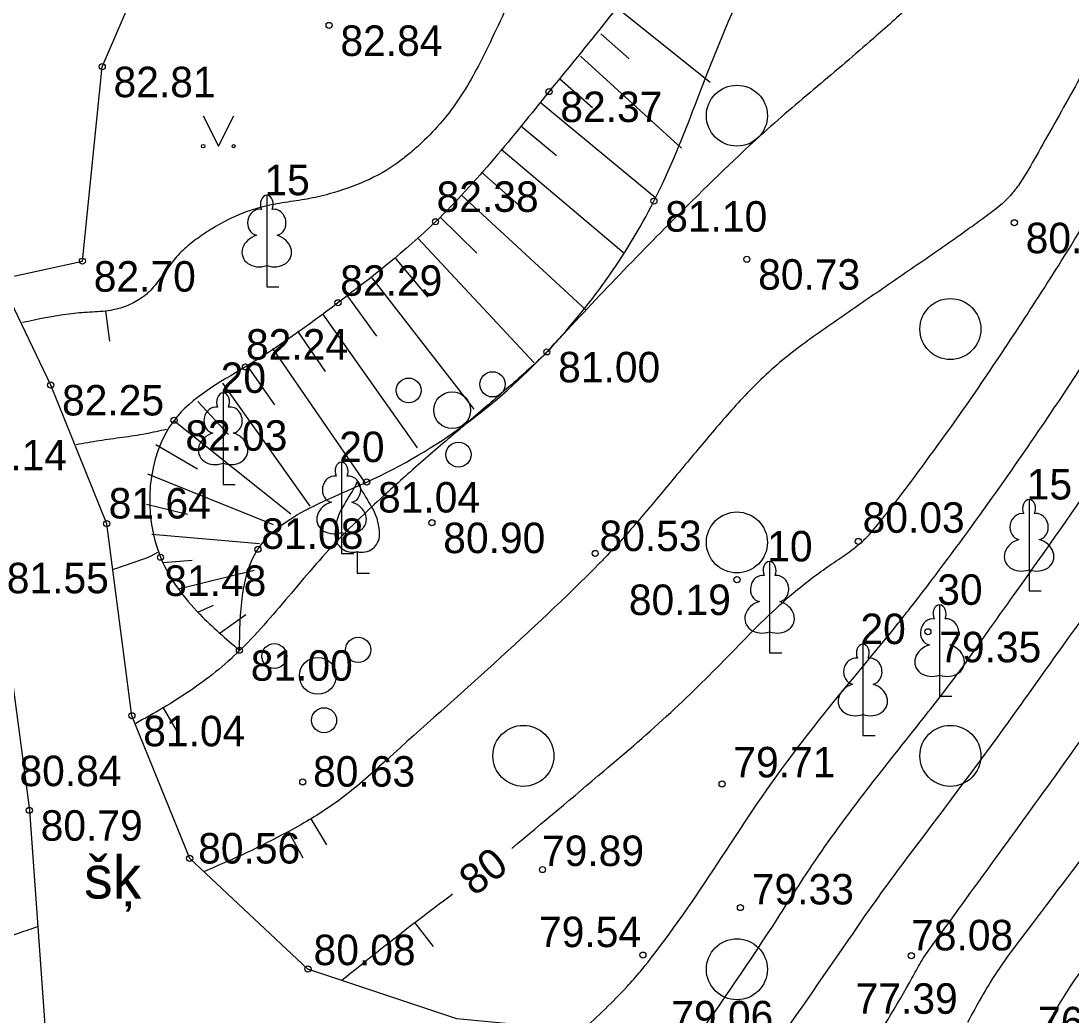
# Model space of a CAD drawing. Extents: x 576692 to 577659, y 273254 to 273799.
# Drawn here: x 577229.26 to 577246.48, y 273433.25 to 273449.55 of the extents above; entities that cross this region are included whole.
import ezdxf

# ---------------------------------------------------------------- set-up
doc = ezdxf.new("R2010")
doc.units = 0
for name, color, linetype in [('APGR_SARK_####_####_#', 7, 'Continuous'), ('CELI_CAPM_####_####_#', 7, 'Continuous'), ('CELI_CMAL_####_####_#', 7, 'Continuous'), ('DREN_VADP_####_####_#', 7, 'Continuous'), ('GAZE_ELEM_####_####_#', 7, 'Continuous'), ('GEOD_ELEM_####_TKST_#', 7, 'Continuous'), ('GEOD_SITP_####_TKST_#', 7, 'Continuous'), ('HIDT_REZV_####_TKST_#', 7, 'Continuous'), ('LKAN_ELEM_PAST_TKST_#', 7, 'Continuous'), ('RELJ_ELEM_####_####_#', 7, 'Continuous'), ('RELJ_HORZ_PAMT_####_#', 7, 'Continuous'), ('SAKT_ELEM_####_####_#', 7, 'Continuous')]:
    doc.layers.add(name, color=color, linetype=linetype)

msp = doc.modelspace()

# ---------------------------------------------------------------- linework, layer by layer
at = {"layer": 'CELI_CAPM_####_####_#'}
for points in [[(577228.923, 273445.318), (577230.27, 273445.614), (577230.595, 273448.803), (577231.355, 273450.566), (577234.085, 273452.032), (577237.485, 273453.435)], [(577239.967, 273432.847), (577236.409, 273433.185), (577233.967, 273434.004), (577232.029, 273435.819), (577231.081, 273438.157), (577230.668, 273441.308), (577229.75, 273443.582), (577228.923, 273445.318)], [(577226.894, 273444.872), (577228.158, 273442.682), (577228.94, 273440.111), (577229.4, 273436.607), (577229.647, 273433.16), (577229.46, 273430.823), (577228.732, 273429.286), (577226.937, 273426.456), (577227.852, 273423.261), (577230.447, 273423.509), (577231.567, 273426.352), (577233.509, 273429.564), (577235.536, 273430.991), (577239.635, 273431.907)]]:
    msp.add_lwpolyline(points, dxfattribs=at)
at = {"layer": 'DREN_VADP_####_####_#'}
msp.add_spline([(577252.982, 273414.853), (577251.974, 273414.319), (577251.296, 273413.895), (577249.566, 273411.91), (577248.903, 273411.509), (577248.444, 273411.498), (577247.696, 273411.504), (577246.444, 273411.535), (577244.846, 273411.363), (577244.022, 273411.247), (577241.708, 273410.879), (577240.339, 273410.502), (577239, 273410.046), (577237.665, 273409.574), (577236.308, 273409.148), (577232.395, 273408.229), (577230.233, 273408.289), (577228.16, 273408.614), (577226.772, 273408.795), (577225.035, 273408.894), (577216.714, 273409.044), (577215.802, 273409.128), (577214.183, 273409.253), (577210.948, 273409.331), (577207.808, 273409.112), (577206.24, 273408.92), (577204.358, 273408.692), (577200.757, 273408.499), (577197.064, 273408.225), (577195.293, 273408.274), (577193.884, 273408.307), (577192.404, 273408.351), (577191.034, 273408.298), (577188.672, 273408.17), (577187.769, 273408), (577187.12, 273407.732), (577186.576, 273407.527), (577186.03, 273407.46), (577185.261, 273408.176), (577184.947, 273408.486), (577184.626, 273408.818), (577184.295, 273409.183), (577183.826, 273409.606), (577182.671, 273410.193), (577181.38, 273410.806), (577180.079, 273411.403), (577178.701, 273412.153), (577176.151, 273413.713), (577175.37, 273414.363), (577174.894, 273414.947), (577174.466, 273415.545), (577174.114, 273416.004), (577171.235, 273418.393), (577170.422, 273418.755), (577169.358, 273419.229), (577168.284, 273419.699), (577167.376, 273420.223), (577166.523, 273421.019), (577166.325, 273421.442), (577166.264, 273421.836), (577166.208, 273422.249), (577166.113, 273422.474), (577165.735, 273422.577), (577165.493, 273422.415), (577164.833, 273422.237), (577164.536, 273422.311), (577162.044, 273423.335), (577157.906, 273424.803), (577155.548, 273425.078), (577154.221, 273424.995), (577152.73, 273424.792), (577149.601, 273423.667), (577149.132, 273423.331), (577148.389, 273422.813), (577147.644, 273422.309), (577147.083, 273422.041), (577145.741, 273421.593), (577144.586, 273421.422), (577143.433, 273421.242), (577142.637, 273421.093), (577137.334, 273418.585), (577135.002, 273417.571), (577133.759, 273417.478), (577132.689, 273417.77), (577131.611, 273418.15), (577130.554, 273418.322), (577129.877, 273418.108), (577129.214, 273417.682), (577128.473, 273417.311), (577127.7, 273417.376), (577125.9, 273418.627), (577123.805, 273421.904), (577122.752, 273424.503), (577122.635, 273425.088), (577122.595, 273425.692), (577122.541, 273426.294), (577122.379, 273426.874), (577120.633, 273429.122), (577118.876, 273430.502), (577117.365, 273431.308), (577114.934, 273432.161), (577112.354, 273432.529), (577111.381, 273432.669), (577110.378, 273432.861), (577108.182, 273433.552), (577106.895, 273434.234)], degree=3, dxfattribs=at)
at = {"layer": 'GAZE_ELEM_####_####_#'}
for p, q in [((577239.093, 273449.726), (577240.562, 273448.548)), ((577238.769, 273449.345), (577239.233, 273448.93)), ((577238.434, 273448.974), (577240.092, 273447.466)), ((577238.099, 273448.602), (577238.634, 273448.134)), ((577237.777, 273448.22), (577239.671, 273446.65)), ((577237.458, 273447.835), (577238.045, 273447.347)), ((577237.137, 273447.452), (577239.147, 273445.749)), ((577236.812, 273447.072), (577237.424, 273446.534)), ((577236.478, 273446.7), (577238.523, 273444.817)), ((577236.135, 273446.336), (577236.736, 273445.746)), ((577235.777, 273445.987), (577237.677, 273443.946)), ((577235.402, 273445.656), (577235.934, 273445.022)), ((577235.013, 273445.342), (577236.686, 273443.184)), ((577234.614, 273445.041), (577235.094, 273444.386)), ((577234.207, 273444.751), (577235.76, 273442.55)), ((577233.796, 273444.466), (577234.252, 273443.802)), ((577233.384, 273444.183), (577234.904, 273441.972)), ((577232.972, 273443.899), (577233.42, 273443.257)), ((577232.564, 273443.61), (577234, 273441.597)), ((577232.161, 273443.314), (577232.664, 273442.773)), ((577231.771, 273443.002), (577233.686, 273441.47)), ((577231.473, 273442.605), (577232.155, 273442.206)), ((577231.336, 273442.126), (577233.396, 273441.293)), ((577231.32, 273441.627), (577231.991, 273441.465)), ((577231.406, 273441.135), (577233.172, 273440.983)), ((577231.593, 273440.673), (577232.071, 273440.707)), ((577231.844, 273440.241), (577233.084, 273440.545)), ((577232.161, 273439.855), (577232.421, 273439.972)), ((577232.53, 273439.518), (577232.951, 273439.819))]:
    msp.add_line(p, q, dxfattribs=at)
msp.add_spline([(577242.91, 273457.86), (577239.725, 273450.721), (577237.921, 273448.394), (577236.059, 273446.259), (577234.46, 273444.93), (577232.943, 273443.878), (577231.772, 273443.003), (577231.55, 273440.757), (577232.196, 273439.822), (577232.844, 273439.231)], degree=3, dxfattribs=at)
at = {"layer": 'GEOD_ELEM_####_TKST_#'}
msp.add_line((577236.025, 273434.372), (577235.721, 273434.769), dxfattribs=at)
for points in [[(577237.31, 273435.982), (577238.817, 273437.25), (577239.916, 273438.213), (577240.915, 273439.193), (577241.896, 273440.146), (577242.448, 273440.573), (577242.738, 273440.771), (577243.018, 273440.982), (577243.168, 273441.126), (577243.387, 273441.392), (577243.6, 273441.662), (577244.014, 273442.212), (577244.813, 273443.324), (577245.577, 273444.46), (577246.317, 273445.612), (577247.158, 273447.012), (577248.372, 273449.267), (577248.708, 273449.952)], [(577242.989, 273432.39), (577243.833, 273433.786), (577243.979, 273434.05), (577244.056, 273434.183), (577244.109, 273434.259), (577246.227, 273437.18), (577247.574, 273439.066), (577249.555, 273441.831), (577250.237, 273442.898), (577251.648, 273445.512)], [(577230.168, 273442.608), (577230.547, 273442.673), (577230.928, 273442.727), (577231.308, 273442.787), (577231.648, 273442.858)], [(577234.53, 273433.826), (577235.659, 273434.721), (577236.34, 273435.236)], [(577255.711, 273434.536), (577255.546, 273434.378), (577255.423, 273434.179), (577255.334, 273433.957), (577255.275, 273433.726), (577255.251, 273433.553), (577255.249, 273433.38), (577255.278, 273433.047), (577255.332, 273432.714), (577255.384, 273432.382), (577255.406, 273432.049), (577255.393, 273431.875), (577255.352, 273431.705), (577255.285, 273431.538), (577255.194, 273431.373), (577255.069, 273431.225), (577254.994, 273431.168), (577254.909, 273431.122), (577254.731, 273431.075), (577254.543, 273431.072), (577254.355, 273431.07), (577254.18, 273431.022), (577253.884, 273430.789), (577253.746, 273430.581), (577253.635, 273430.359), (577253.523, 273430.14), (577253.38, 273429.943), (577253.105, 273429.645), (577252.819, 273429.36), (577252.519, 273429.095), (577252.199, 273428.852), (577251.899, 273428.646), (577251.649, 273428.477), (577250.896, 273427.978), (577250.396, 273427.641), (577250.148, 273427.47), (577249.902, 273427.295), (577249.672, 273427.116), (577249.45, 273426.925), (577249.232, 273426.73), (577249.01, 273426.54), (577248.703, 273426.289), (577248.214, 273425.925), (577245.673, 273423.793), (577245.544, 273423.668), (577245.335, 273423.423), (577245.132, 273423.166)]]:
    msp.add_spline(points, degree=3, dxfattribs=at)
at = {"layer": 'GEOD_SITP_####_TKST_#'}
for p, q in [((577230.717, 273444.3), (577230.656, 273444.796)), ((577231.85, 273437.857), (577231.598, 273438.289)), ((577234.275, 273436.038), (577234.021, 273436.468)), ((577233.887, 273435.82), (577233.649, 273436.26))]:
    msp.add_line(p, q, dxfattribs=at)
for points in [[(577248.408, 273456.577), (577248.253, 273456.237), (577247.855, 273455.516), (577247.448, 273454.733), (577247.054, 273453.943), (577246.659, 273453.152), (577246.247, 273452.369), (577245.6, 273451.5), (577245.025, 273450.923), (577244.44, 273450.36), (577243.845, 273449.809), (577243.24, 273449.268), (577242.777, 273448.869), (577242.311, 273448.475), (577241.846, 273448.079), (577241.389, 273447.674), (577240.023, 273446.358), (577237.898, 273444.133), (577237.886, 273444.12), (577237.867, 273444.101), (577237.22, 273443.515), (577236.558, 273442.945), (577235.895, 273442.377), (577235.243, 273441.796), (577234.519, 273441.099), (577234.099, 273440.643), (577233.697, 273440.171), (577233.293, 273439.701), (577232.869, 273439.249), (577232.846, 273439.227), (577232.842, 273439.223), (577232.036, 273438.569), (577231.595, 273438.287), (577231.144, 273438.032)], [(577242.058, 273455.968), (577241.903, 273455.789), (577241.747, 273455.608), (577241.462, 273455.227), (577239.94, 273452.789), (577239.849, 273452.645), (577239.724, 273452.516), (577239.43, 273452.321), (577239.106, 273452.169), (577238.786, 273452.01), (577238.505, 273451.795), (577238.355, 273451.63), (577238.212, 273451.462), (577237.948, 273451.113), (577237.713, 273450.748), (577237.506, 273450.365), (577236.99, 273449.277), (577236.728, 273448.754), (577236.487, 273448.341), (577236.206, 273447.956), (577235.88, 273447.602), (577235.699, 273447.436), (577235.507, 273447.279), (577234.975, 273446.955), (577234.402, 273446.741), (577234.046, 273446.65), (577233.683, 273446.59), (577233.322, 273446.526), (577232.968, 273446.426), (577232.461, 273446.186), (577232.224, 273446.034), (577231.997, 273445.863), (577231.791, 273445.66), (577231.616, 273445.425), (577231.438, 273445.193), (577231.338, 273445.087), (577231.281, 273445.041), (577231.219, 273444.998), (577230.985, 273444.876), (577230.735, 273444.807), (577230.563, 273444.787), (577230.391, 273444.776), (577230.219, 273444.765), (577230.048, 273444.747), (577229.288, 273444.605)], [(577249.575, 273455.482), (577249.485, 273455.222), (577249.43, 273455.059), (577249.335, 273454.759), (577249.245, 273454.458), (577249.156, 273454.156), (577249.061, 273453.856), (577248.645, 273452.759), (577248.411, 273452.221), (577248.17, 273451.684), (577247.645, 273450.575), (577247.089, 273449.485), (577246.507, 273448.407), (577245.905, 273447.334), (577245.65, 273446.907), (577245.501, 273446.71), (577245.326, 273446.536), (577245.066, 273446.334), (577244.799, 273446.142), (577244.049, 273445.616), (577243.294, 273445.097), (577242.541, 273444.574), (577241.8, 273444.033), (577241.093, 273443.367), (577240.53, 273442.726), (577239.984, 273442.072), (577239.437, 273441.419), (577238.871, 273440.784), (577238.748, 273440.658), (577235.26, 273437.435), (577234.551, 273436.828), (577233.901, 273436.399), (577233.501, 273436.181), (577233.097, 273435.975), (577232.27, 273435.604)], [(577238.465, 273432.992), (577239.2, 273433.717), (577239.418, 273433.965), (577239.734, 273434.366), (577240.902, 273436.063), (577241.25, 273436.591), (577242.601, 273438.403), (577243.641, 273439.669), (577243.837, 273439.918), (577245.953, 273442.834), (577247.249, 273444.846), (577248.916, 273447.851), (577250.42, 273450.936), (577250.943, 273452.34), (577251.155, 273452.959), (577251.484, 273453.704)], [(577240.276, 273432.78), (577241.672, 273434.839), (577242.23, 273435.702), (577244.06, 273438.12), (577244.676, 273438.923), (577245.026, 273439.413), (577245.536, 273440.129), (577246.905, 273442.085), (577247.577, 273443.071), (577248.242, 273444.064), (577248.782, 273444.993), (577250.646, 273448.677), (577251.416, 273450.272), (577251.693, 273450.991), (577251.991, 273451.827), (577252.437, 273452.815)], [(577241.457, 273432.508), (577242.849, 273434.507), (577243.117, 273434.896), (577243.954, 273436.038), (577245.451, 273438.052), (577246.3, 273439.24), (577247.541, 273440.978), (577249.165, 273443.524), (577252.22, 273449.224), (577252.357, 273449.493), (577252.413, 273449.609), (577252.434, 273449.66), (577252.826, 273450.695), (577253.389, 273451.89)], [(577255.267, 273450.117), (577254.891, 273449.377), (577254.49, 273448.441), (577254.279, 273447.983), (577251.699, 273443.039), (577251.314, 273442.346), (577251.137, 273442.074), (577249.369, 273439.639), (577248.836, 273438.894), (577247.007, 273436.303), (577245.652, 273434.495), (577245.256, 273433.946), (577244.78, 273433.126)], [(577256.236, 273449.251), (577255.786, 273448.386), (577255.32, 273447.317), (577255.237, 273447.14), (577254.2, 273445.187), (577252.393, 273441.99), (577251.595, 273440.737), (577249.946, 273438.448), (577249.632, 273438.021), (577248.523, 273436.46), (577247.792, 273435.421), (577247.248, 273434.738), (577246.457, 273433.709), (577246.042, 273433.007)], [(577230.767, 273440.557), (577230.795, 273440.566), (577230.833, 273440.58), (577231.459, 273440.814), (577231.509, 273440.842)], [(577229.528, 273434.696), (577228.811, 273434.44), (577228.093, 273434.163), (577227.077, 273433.74), (577226.625, 273433.614), (577225.865, 273433.58), (577224.619, 273433.686), (577222.91, 273433.78), (577222.886, 273433.785), (577222.863, 273433.793), (577222.831, 273433.805), (577218.391, 273435.021), (577215.702, 273435.502), (577212.683, 273435.835), (577211.95, 273435.848), (577210.689, 273435.795), (577208.153, 273435.708), (577204.598, 273435.61), (577203.143, 273435.592), (577196.078, 273435.666), (577195.486, 273435.681), (577195.463, 273435.683), (577195.34, 273435.701), (577194.109, 273435.908), (577192.883, 273436.138), (577191.66, 273436.393), (577190.441, 273436.675), (577188.159, 273437.582), (577187.574, 273437.944), (577187.005, 273438.321), (577186.056, 273439.02)]]:
    msp.add_spline(points, degree=3, dxfattribs=at)
at = {"layer": 'LKAN_ELEM_PAST_TKST_#'}
for p, q in [((577232.25, 273448), (577232.5, 273447.5)), ((577232.5, 273447.5), (577232.75, 273448)), ((577233.293, 273445.542), (577233.293, 273445.195)), ((577233.293, 273445.195), (577233.493, 273445.195)), ((577232.576, 273442.299), (577232.576, 273441.952)), ((577232.576, 273441.952), (577232.776, 273441.952)), ((577234.519, 273441.165), (577234.519, 273440.818)), ((577234.519, 273440.818), (577234.719, 273440.818)), ((577234.776, 273440.85), (577234.776, 273440.498)), ((577245.791, 273440.552), (577245.791, 273440.205)), ((577234.776, 273440.498), (577234.976, 273440.498)), ((577245.791, 273440.205), (577245.991, 273440.205)), ((577241.537, 273439.536), (577241.537, 273439.189)), ((577241.537, 273439.189), (577241.737, 273439.189)), ((577244.324, 273438.824), (577244.324, 273438.477)), ((577244.324, 273438.477), (577244.524, 273438.477)), ((577243.065, 273438.18), (577243.065, 273437.833)), ((577243.065, 273437.833), (577243.265, 273437.833))]:
    msp.add_line(p, q, dxfattribs=at)
for points in [[(577233.293, 273446.695), (577233.293, 273445.542)], [(577233.383, 273446.463), (577233.382, 273446.464)], [(577232.576, 273443.452), (577232.576, 273442.299)], [(577232.666, 273443.22), (577232.665, 273443.221)], [(577234.519, 273442.318), (577234.519, 273441.165)], [(577234.609, 273442.086), (577234.608, 273442.087)], [(577245.791, 273441.705), (577245.791, 273440.552)], [(577245.881, 273441.473), (577245.88, 273441.474)], [(577241.537, 273440.689), (577241.537, 273439.536)], [(577241.627, 273440.457), (577241.626, 273440.458)], [(577244.324, 273439.977), (577244.324, 273438.824)], [(577244.414, 273439.745), (577244.413, 273439.746)], [(577243.065, 273439.333), (577243.065, 273438.18)], [(577243.155, 273439.101), (577243.154, 273439.102)]]:
    msp.add_lwpolyline(points, dxfattribs=at)
for centre, radius in [((577241, 273448), 0.5), ((577232.25, 273447.5), 0.028), ((577232.75, 273447.5), 0.0263), ((577244.5, 273444.5), 0.5), ((577236.994, 273443.594), 0.207), ((577235.619, 273443.493), 0.204), ((577236.333, 273443.169), 0.301), ((577236.436, 273442.441), 0.205), ((577241, 273441), 0.5), ((577233.416, 273439.137), 0.204), ((577234.791, 273439.238), 0.207), ((577234.13, 273438.813), 0.301), ((577234.233, 273438.085), 0.205), ((577237.5, 273437.5), 0.5), ((577244.5, 273437.5), 0.5), ((577241, 273434), 0.5)]:
    msp.add_circle(centre, radius, dxfattribs=at)
for centre, radius, start, end in [((577234.359, 273442.136), 0.439, 324.3837, 341.712), ((577235.193, 273442.136), 0.439, 198.288, 215.6163), ((577247.401, 273434.102), 14.88, 148.4844, 149.9901), ((577222.151, 273434.102), 14.88, 30.0099, 31.5156), ((577235.3, 273441.123), 0.89, 151.757, 179.9138), ((577234.252, 273441.123), 0.89, 0.0862, 28.243), ((577234.7, 273441.129), 0.29, 181.0782, 285.2823), ((577234.852, 273441.129), 0.29, 254.7177, 358.9218)]:
    msp.add_arc(centre, radius, start, end, dxfattribs=at)
for centre, major_axis, ratio, start_param, end_param in [((577233.293, 273446.545), (0, -0.15), 0.707107, 3.14537, 5.287485), ((577233.293, 273446.545), (0, -0.15), 0.707107, 0.995701, 3.137816), ((577233.165, 273446.25), (-0.039, -0.212), 0.861323, 3.141593, 6.283185), ((577233.421, 273446.25), (0.039, -0.212), 0.861323, 0, 3.141593), ((577233.203, 273445.788), (0.307, 0.095), 0.814445, 1.570796, 4.752015), ((577233.383, 273445.788), (-0.307, 0.095), 0.814445, 1.531171, 4.712389), ((577232.576, 273443.302), (0, -0.15), 0.707107, 3.14537, 5.287485), ((577232.576, 273443.302), (0, -0.15), 0.707107, 0.995701, 3.137816), ((577232.448, 273443.007), (-0.039, -0.212), 0.861323, 3.141593, 6.283185), ((577232.704, 273443.007), (0.039, -0.212), 0.861323, 0, 3.141593), ((577232.486, 273442.545), (0.307, 0.095), 0.814445, 1.570796, 4.752015), ((577232.666, 273442.545), (-0.307, 0.095), 0.814445, 1.531171, 4.712389), ((577234.519, 273442.168), (0, -0.15), 0.707107, 3.14537, 5.287485), ((577234.519, 273442.168), (0, -0.15), 0.707107, 0.995701, 3.137816), ((577234.391, 273441.873), (-0.039, -0.212), 0.861323, 3.141593, 6.283185), ((577234.647, 273441.873), (0.039, -0.212), 0.861323, 0, 3.141593), ((577234.429, 273441.411), (0.307, 0.095), 0.814445, 1.570796, 4.752015), ((577234.609, 273441.411), (-0.307, 0.095), 0.814445, 1.531171, 4.712389), ((577245.791, 273441.555), (0, -0.15), 0.707107, 3.14537, 5.287485), ((577245.791, 273441.555), (0, -0.15), 0.707107, 0.995701, 3.137816), ((577245.663, 273441.26), (-0.039, -0.212), 0.861323, 3.141593, 6.283185), ((577245.919, 273441.26), (0.039, -0.212), 0.861323, 0, 3.141593), ((577245.701, 273440.798), (0.307, 0.095), 0.814445, 1.570796, 4.752015), ((577245.881, 273440.798), (-0.307, 0.095), 0.814445, 1.531171, 4.712389), ((577241.537, 273440.539), (0, -0.15), 0.707107, 3.14537, 5.287485), ((577241.537, 273440.539), (0, -0.15), 0.707107, 0.995701, 3.137816), ((577241.409, 273440.244), (-0.039, -0.212), 0.861323, 3.141593, 6.283185), ((577241.665, 273440.244), (0.039, -0.212), 0.861323, 0, 3.141593), ((577241.447, 273439.782), (0.307, 0.095), 0.814445, 1.570796, 4.752015), ((577241.627, 273439.782), (-0.307, 0.095), 0.814445, 1.531171, 4.712389), ((577244.324, 273439.827), (0, -0.15), 0.707107, 3.14537, 5.287485), ((577244.324, 273439.827), (0, -0.15), 0.707107, 0.995701, 3.137816), ((577244.196, 273439.532), (-0.039, -0.212), 0.861323, 3.141593, 6.283185), ((577244.452, 273439.532), (0.039, -0.212), 0.861323, 0, 3.141593), ((577243.065, 273439.183), (0, -0.15), 0.707107, 3.14537, 5.287485), ((577243.065, 273439.183), (0, -0.15), 0.707107, 0.995701, 3.137816), ((577244.234, 273439.07), (0.307, 0.095), 0.814445, 1.570796, 4.752015), ((577244.414, 273439.07), (-0.307, 0.095), 0.814445, 1.531171, 4.712389), ((577242.937, 273438.888), (-0.039, -0.212), 0.861323, 3.141593, 6.283185), ((577243.193, 273438.888), (0.039, -0.212), 0.861323, 0, 3.141593), ((577242.975, 273438.426), (0.307, 0.095), 0.814445, 1.570796, 4.752015), ((577243.155, 273438.426), (-0.307, 0.095), 0.814445, 1.531171, 4.712389)]:
    msp.add_ellipse(centre, major_axis=major_axis, ratio=ratio, start_param=start_param, end_param=end_param, dxfattribs=at)
at = {"layer": 'RELJ_ELEM_####_####_#'}
for centre in [(577234.314, 273449.48), (577230.595, 273448.803), (577237.92, 273448.395), (577239.639, 273446.598), (577236.059, 273446.26), (577245.549, 273446.244), (577241.163, 273445.646), (577230.27, 273445.614), (577234.46, 273444.931), (577237.884, 273444.126), (577232.943, 273443.879), (577229.75, 273443.583), (577231.772, 273443.004), (577234.931, 273441.991), (577230.668, 273441.309), (577236, 273441.325), (577242.991, 273441.017), (577233.147, 273440.889), (577238.677, 273440.82), (577231.55, 273440.757), (577241.002, 273440.39), (577244.132, 273439.535), (577232.844, 273439.232), (577231.081, 273438.157), (577233.882, 273437.073), (577240.757, 273437.039), (577229.4, 273436.608), (577232.029, 273435.82), (577237.813, 273435.635), (577241.059, 273435.012), (577239.46, 273434.232), (577243.861, 273434.221), (577233.968, 273434.004)]:
    msp.add_circle(centre, 0.05, dxfattribs=at)
at = {"layer": 'SAKT_ELEM_####_####_#'}
msp.add_spline([(577232.844, 273439.231), (577233.147, 273440.888), (577234.931, 273441.99), (577237.884, 273444.125), (577239.64, 273446.597), (577241.781, 273451.179), (577244.2, 273453.762), (577245.686, 273457.321)], degree=3, dxfattribs=at)

# ---------------------------------------------------------------- texts
at = {"layer": 'APGR_SARK_####_####_#'}
for s, p in [(' 15', (577233.068, 273446.695)), (' 20', (577232.351, 273443.452)), (' 20', (577234.294, 273442.318)), (' 15', (577245.566, 273441.705)), (' 10', (577241.312, 273440.689)), (' 30', (577244.099, 273439.977)), (' 20', (577242.84, 273439.333))]:
    msp.add_text(s, height=0.5, dxfattribs=at).set_placement(p)
at = {"layer": 'CELI_CMAL_####_####_#'}
msp.add_text('šķ', height=0.7, dxfattribs=at).set_placement((577230.298, 273435.16))
at = {"layer": 'HIDT_REZV_####_TKST_#'}
for s, p in [(' 82.84', (577234.314, 273448.98)), (' 82.81', (577230.595, 273448.303)), (' 82.37', (577237.92, 273447.895)), (' 82.38', (577235.891, 273446.422)), (' 81.10', (577239.639, 273446.098)), (' 80.45', (577245.549, 273445.744)), (' 82.70', (577230.27, 273445.114)), (' 82.29', (577234.311, 273445.046)), (' 80.73', (577241.163, 273445.146)), (' 82.24', (577232.766, 273443.999)), (' 81.00', (577237.884, 273443.626)), (' 82.25', (577229.75, 273443.083)), (' 82.03', (577231.772, 273442.504)), (' 82.14', (577228.158, 273442.183)), (' 81.64', (577230.515, 273441.393)), (' 81.04', (577234.931, 273441.491)), (' 80.03', (577242.876, 273441.159)), (' 81.08', (577233.018, 273440.895)), (' 80.90', (577236, 273440.825)), (' 80.53', (577238.562, 273440.859)), (' 81.55', (577228.844, 273440.167)), (' 81.48', (577231.426, 273440.123)), (' 80.19', (577239.043, 273439.81)), (' 79.35', (577244.132, 273439.035)), (' 81.00', (577232.844, 273438.732)), (' 81.04', (577231.081, 273437.657)), (' 79.71', (577240.757, 273437.147)), (' 80.84', (577229.052, 273437.003)), (' 80.63', (577233.866, 273436.995)), (' 80.79', (577229.4, 273436.108)), (' 80.56', (577231.982, 273435.734)), (' 79.89', (577237.619, 273435.693)), (' 79.33', (577241.059, 273435.063)), (' 79.54', (577237.57, 273434.363)), (' 78.08', (577243.671, 273434.31)), (' 80.08', (577233.874, 273434.067)), (' 77.39', (577242.762, 273433.27)), (' 79.06', (577239.738, 273432.981)), (' 76.27', (577245.752, 273432.884))]:
    msp.add_text(s, height=0.5, dxfattribs=at).set_placement(p)
at = {"layer": 'RELJ_HORZ_PAMT_####_#'}
msp.add_text('80', height=0.5, rotation=37.159, dxfattribs=at).set_placement((577236.692, 273435.186))

doc.saveas('drawing.dxf')
